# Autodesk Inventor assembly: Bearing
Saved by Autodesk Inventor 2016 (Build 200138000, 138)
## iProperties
Created: 2015-08
Part Number: Bearing
Document SubType Name: Assembly
Designer: stank
ClientObjectVersion: 1
Author: stank
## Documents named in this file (2)
- E:\Turbokompr\Sklop turbokompresora\Design Accelerator\Bearing4.iam
- C:\Users\stank\Documents\Inventor\Content Center Files\R2016\en-US\BS 292 (V)\BS 292_ Part 1 - N 1005 - 25 x 47 x 12.ipt
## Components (1 placed, 1 different names)
1. BS 292: Part 1 (V) (Metric) N 1005 - 25 x 47 x 12:1
